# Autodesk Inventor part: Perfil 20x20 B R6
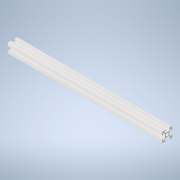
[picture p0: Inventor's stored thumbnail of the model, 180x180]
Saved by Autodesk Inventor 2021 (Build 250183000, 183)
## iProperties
Created: 2020-12
Part Number: Perfil 20x20 B R6
Material: Genérico
Document SubType Name: Modeling
Designer: ATOUZA
Density: 1 g/cm^3
Appearance: Valor por defecto
Author: ATOUZA
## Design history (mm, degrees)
sketch "Boceto1"
  geometry: L1 (4.5, 0.954)-(4.5, 3.232); L2 (4.646, 3.586)-(6.914, 5.854); L3 (7.268, 6)-(8, 6); L4 (8.5, 5.5)-(8.5, 3.6); L5 (9, 3.1)-(9.3, 3.1); L6 (9.5, 3.3)-(9.5, 3.65); L7 (9.5, 3.65)-(9.8, 3.65); L8 (10, 3.85)-(10, 8.5); L9 (8.5, 10)-(3.85, 10); L10 (3.65, 9.8)-(3.65, 9.5); L11 (3.65, 9.5)-(3.3, 9.5); L12 (3.1, 9.3)-(3.1, 9); L13 (3.6, 8.5)-(5.5, 8.5); L14 (6, 8)-(6, 7.268); L15 (5.854, 6.914)-(3.586, 4.646); L16 (3.232, 4.5)-(0.954, 4.5); L17 (0.854, 4.473)-(0.1, 4.038); L18 (-0.1, 4.038)-(-0.854, 4.473); L19 (-0.954, 4.5)-(-3.232, 4.5); L20 (-3.586, 4.646)-(-5.854, 6.914); L21 (-6, 7.268)-(-6, 8); L22 (-5.5, 8.5)-(-3.6, 8.5); L23 (-3.1, 9)-(-3.1, 9.3); L24 (-3.3, 9.5)-(-3.65, 9.5); L25 (-3.65, 9.5)-(-3.65, 9.8); L26 (-3.85, 10)-(-8.5, 10); L27 (-10, 8.5)-(-10, 3.85); L28 (-9.8, 3.65)-(-9.5, 3.65); L29 (-9.5, 3.65)-(-9.5, 3.3); L30 (-9.3, 3.1)-(-9, 3.1); L31 (-8.5, 3.6)-(-8.5, 5.5); L32 (-8, 6)-(-7.268, 6); L33 (-6.914, 5.854)-(-4.646, 3.586); L34 (-4.5, 3.232)-(-4.5, 0.954); L35 (-4.473, 0.854)-(-4.038, 0.1); L36 (-4.038, -0.1)-(-4.473, -0.854); L37 (-4.5, -0.954)-(-4.5, -3.232); L38 (-4.646, -3.586)-(-6.914, -5.854); L39 (-7.268, -6)-(-8, -6); L40 (-8.5, -5.5)-(-8.5, -3.6); L41 (-9, -3.1)-(-9.3, -3.1); L42 (-9.5, -3.3)-(-9.5, -3.65); L43 (-9.5, -3.65)-(-9.8, -3.65); L44 (-10, -3.85)-(-10, -8.5); L45 (-8.5, -10)-(-3.85, -10); L46 (-3.65, -9.8)-(-3.65, -9.5); L47 (-3.65, -9.5)-(-3.3, -9.5); L48 (-3.1, -9.3)-(-3.1, -9); L49 (-3.6, -8.5)-(-5.5, -8.5); L50 (-6, -8)-(-6, -7.268); L51 (-5.854, -6.914)-(-3.586, -4.646); L52 (-3.232, -4.5)-(-0.954, -4.5); L53 (1.258, -2.445)-(1.914, -2.99); L54 (2.992, -1.91)-(2.445, -1.258); L55 (2.445, 1.258)-(2.992, 1.91); L56 (1.914, 2.99)-(1.258, 2.445); L57 (-1.258, 2.445)-(-1.914, 2.99); L58 (-2.992, 1.91)-(-2.445, 1.258); L59 (-2.445, -1.258)-(-2.992, -1.91); L60 (-1.914, -2.99)-(-1.258, -2.445); L61 (1.258, -2.445)-(1.914, -2.99); L62 (2.992, -1.91)-(2.445, -1.258); L63 (2.445, 1.258)-(2.992, 1.91); L64 (1.914, 2.99)-(1.258, 2.445)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; A1 r 0.5 centre (5, 3.232) between (4.646, 3.586) and (4.5, 3.232); A2 r 0.5 centre (7.268, 5.5) between (7.268, 6) and (6.914, 5.854); A3 r 0.5 centre (8, 5.5) between (8.5, 5.5) and (8, 6); A4 r 0.5 centre (9, 3.6) between (8.5, 3.6) and (9, 3.1); A5 r 0.2 centre (9.3, 3.3) between (9.3, 3.1) and (9.5, 3.3); A6 r 0.2 centre (9.8, 3.85) between (9.8, 3.65) and (10, 3.85); A7 r 1.5 centre (8.5, 8.5) between (10, 8.5) and (8.5, 10); A8 r 0.2 centre (3.85, 9.8) between (3.85, 10) and (3.65, 9.8); A9 r 0.2 centre (3.3, 9.3) between (3.3, 9.5) and (3.1, 9.3); A10 r 0.5 centre (3.6, 9) between (3.1, 9) and (3.6, 8.5); A11 r 0.5 centre (5.5, 8) between (6, 8) and (5.5, 8.5); A12 r 0.5 centre (5.5, 7.268) between (5.854, 6.914) and (6, 7.268); A13 r 0.5 centre (3.232, 5) between (3.232, 4.5) and (3.586, 4.646); A14 r 0.2 centre (0.954, 4.3) between (0.954, 4.5) and (0.854, 4.473); A15 r 0.2 centre (0, 4.211) between (-0.1, 4.038) and (0.1, 4.038); A16 r 0.2 centre (-0.954, 4.3) between (-0.854, 4.473) and (-0.954, 4.5); A17 r 0.5 centre (-3.232, 5) between (-3.586, 4.646) and (-3.232, 4.5); A18 r 0.5 centre (-5.5, 7.268) between (-6, 7.268) and (-5.854, 6.914); A19 r 0.5 centre (-5.5, 8) between (-5.5, 8.5) and (-6, 8); A20 r 0.5 centre (-3.6, 9) between (-3.6, 8.5) and (-3.1, 9); A21 r 0.2 centre (-3.3, 9.3) between (-3.1, 9.3) and (-3.3, 9.5); A22 r 0.2 centre (-3.85, 9.8) between (-3.65, 9.8) and (-3.85, 10); A23 r 1.5 centre (-8.5, 8.5) between (-8.5, 10) and (-10, 8.5); A24 r 0.2 centre (-9.8, 3.85) between (-10, 3.85) and (-9.8, 3.65); A25 r 0.2 centre (-9.3, 3.3) between (-9.5, 3.3) and (-9.3, 3.1); A26 r 0.5 centre (-9, 3.6) between (-9, 3.1) and (-8.5, 3.6); A27 r 0.5 centre (-8, 5.5) between (-8, 6) and (-8.5, 5.5); A28 r 0.5 centre (-7.268, 5.5) between (-6.914, 5.854) and (-7.268, 6); A29 r 0.5 centre (-5, 3.232) between (-4.5, 3.232) and (-4.646, 3.586); A30 r 0.2 centre (-4.3, 0.954) between (-4.5, 0.954) and (-4.473, 0.854); A31 r 0.2 centre (-4.211, 0) between (-4.038, -0.1) and (-4.038, 0.1); A32 r 0.2 centre (-4.3, -0.954) between (-4.473, -0.854) and (-4.5, -0.954); A33 r 0.5 centre (-5, -3.232) between (-4.646, -3.586) and (-4.5, -3.232); A34 r 0.5 centre (-7.268, -5.5) between (-7.268, -6) and (-6.914, -5.854); A35 r 0.5 centre (-8, -5.5) between (-8.5, -5.5) and (-8, -6); A36 r 0.5 centre (-9, -3.6) between (-8.5, -3.6) and (-9, -3.1); A37 r 0.2 centre (-9.3, -3.3) between (-9.3, -3.1) and (-9.5, -3.3); A38 r 0.2 centre (-9.8, -3.85) between (-9.8, -3.65) and (-10, -3.85); A39 r 1.5 centre (-8.5, -8.5) between (-10, -8.5) and (-8.5, -10); A40 r 0.2 centre (-3.85, -9.8) between (-3.85, -10) and (-3.65, -9.8); A41 r 0.2 centre (-3.3, -9.3) between (-3.3, -9.5) and (-3.1, -9.3); A42 r 0.5 centre (-3.6, -9) between (-3.1, -9) and (-3.6, -8.5); A43 r 0.5 centre (-5.5, -8) between (-6, -8) and (-5.5, -8.5); A44 r 0.5 centre (-5.5, -7.268) between (-5.854, -6.914) and (-6, -7.268); A45 r 0.5 centre (-3.232, -5) between (-3.232, -4.5) and (-3.586, -4.646); A46 r 2.75 centre (0, 0) between (-1.258, -2.445) and (1.258, -2.445); A47 r 3.55 centre (0, 0) between (1.914, -2.99) and (2.992, -1.91); A48 r 2.75 centre (0, 0) between (2.445, -1.258) and (2.445, 1.258); A49 r 3.55 centre (0, 0) between (2.992, 1.91) and (1.914, 2.99); A50 r 2.75 centre (0, 0) between (1.258, 2.445) and (-1.258, 2.445); A51 r 3.55 centre (0, 0) between (-1.914, 2.99) and (-2.992, 1.91); A52 r 2.75 centre (0, 0) between (-2.445, 1.258) and (-2.445, -1.258); A53 r 3.55 centre (0, 0) between (-2.992, -1.91) and (-1.914, -2.99); A54 r 2.75 centre (0, 0) between (-1.258, -2.445) and (1.258, -2.445); A55 r 3.55 centre (0, 0) between (1.914, -2.99) and (2.992, -1.91); A56 r 2.75 centre (0, 0) between (2.445, -1.258) and (2.445, 1.258); A57 r 3.55 centre (0, 0) between (2.992, 1.91) and (1.914, 2.99); A58 r 2.75 centre (0, 0) between (1.258, 2.445) and (-1.258, 2.445); A59 r 3.55 centre (0, 0) between (-1.914, 2.99) and (-2.992, 1.91); A60 r 2.75 centre (0, 0) between (-2.445, 1.258) and (-2.445, -1.258); A61 r 3.55 centre (0, 0) between (-2.992, -1.91) and (-1.914, -2.99); A62 r 0.5 centre (-8, -5.5) between (-8.5, -5.5) and (-8, -6); A63 r 0.2 centre (-4.211, 0) between (-4.038, -0.1) and (-4.038, 0.1); A64 r 0.5 centre (-7.268, 5.5) between (-6.914, 5.854) and (-7.268, 6)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; 1 further point
  constraints: 324 end point, 198 point on circle, 99 centre point, 2 point on line, 6 other
extrude "Extrusión1" new body sketch "Boceto1" distance "d0" = 310; taper "d1" = 0 deg
node "Sólido1"
